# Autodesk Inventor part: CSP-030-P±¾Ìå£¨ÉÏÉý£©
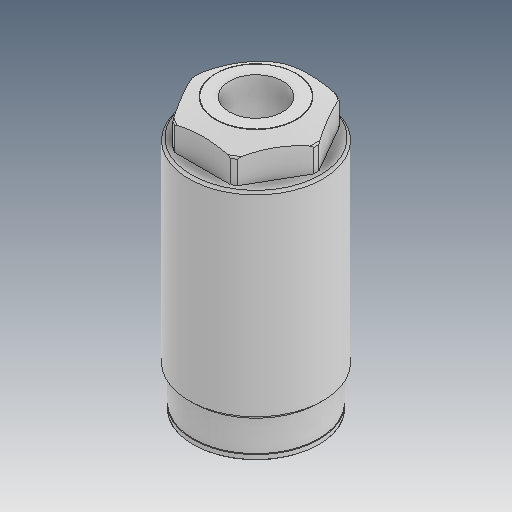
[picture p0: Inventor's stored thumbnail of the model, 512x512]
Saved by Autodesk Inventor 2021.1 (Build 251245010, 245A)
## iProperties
Created: 2019-01
Part Number: CSP-030-P±¾Ìå£¨ÉÏÉý£©
Material: Ogólny
Document SubType Name: Modeling
Designer: user
Density: 1 g/cm^3
Appearance: Domyślna
Author: user
Revision Number: ÈÎºÎ
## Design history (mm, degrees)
feature "ÇÐ³ý-À­Éì5"
node "Bryła1"
